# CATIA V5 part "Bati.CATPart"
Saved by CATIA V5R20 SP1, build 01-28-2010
Part number: Bati
Publications: "Corps principal"
Bounding box of the stored display mesh (mm): x -17.479 to 17.479, y -15.2 to 67.3, z -21.828 to 5.5
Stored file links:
  C:\Documents and Settings\pschann\Bureau\IAO\Bati.CATPart
  C:\Documents and Settings\pschann\Bureau\IAO\pschann.CATProduct
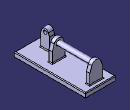
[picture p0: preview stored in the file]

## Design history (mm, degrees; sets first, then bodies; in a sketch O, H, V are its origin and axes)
External parameters (linked from other documents)
  `External.Diamètre coulisseau` = 10 mm
  `External.Epaisseur pivot` = 2 mm
  External.AB = 10 mm
  `External.Diamètre pivot` = 4 mm
  External.BC = 41 mm
  `External.Longueur axe pivot` = 6 mm
Set1
  Line1: linked copy from another document
  Line2: linked copy from another document
Body1 (main body)
  Sketch1 on zx-plane, origin (0, 0, 0), H (-1, 0, 0), V (0, 0, 1)
    circle A1 centre (0, 0) radius 3
    point P1 (0, 0)
    radius A1 = 3 {= `External.Diamètre coulisseau` /2-`External.Epaisseur pivot`}
    coincidence: P1 O
  Pad1: profile Sketch1, direction (0, -1, 0), length -16.8 {= (-External.AB -`External.Diamètre pivot` )*1.20}, opposite side length 58.3 {= (External.AB +External.BC+`External.Diamètre pivot` /2 )*1.1}
  Sketch2 on start face of Pad1, origin (0, 58.3, 0), H (-1, 0, 0), V (0, 0, 1)
    arc A1 centre (0, 0) radius 5.5 from (5.2004, 1.7906) to (-5.2004, 1.7906) ccw
    point P1 (-5.2004, 1.7906)
    point P2 (5.2004, 1.7906)
    reference projected line E1 (0, 12) -> (0, 0) from Line1
    line L1 (5.2004, 1.7906) -> (7.4793, -4.828)
    line L2 (-5.2004, 1.7906) -> (-7.4793, -4.828)
    point P4 (-7.4793, -4.828)
    line L3 (-7.4793, -4.828) -> (-7.4793, -16.828)
    point P6 (-7.4793, -4.828)
    line L4 (7.4793, -4.828) -> (7.4793, -16.828)
    line L5 (7.4793, -16.828) -> (-7.4793, -16.828)
    length L2 = 7
    length L1 = 7 {= Sketch2.length(L2)}
    length L4 = 12 {= External.AB *1.2}
    radius A1 = 5.5
    angle L2 L1 = 38
    symmetry: P2 P1 E1
    tangency: L1 A1, L2 A1
    vertical: L4 V, L3 V
    coincidence: P6 P4
    horizontal: L5 H
  Pad2: profile Sketch2, direction (0, 1, 0), length 4
  Sketch3 on end face of Pad1, origin (0, 16.8, 0), H (1, 0, 0), V (0, 0, 1)
    point P1 (-5.2004, 1.7906)
    point P2 (5.2004, 1.7906)
    arc A1 centre (0, 0) radius 5.5 from (5.2004, 1.7906) to (-5.2004, 1.7906) ccw
    line L1 (5.2004, 1.7906) -> (7.4793, -4.828)
    point P5 (-7.4793, -4.828)
    line L2 (-5.2004, 1.7906) -> (-7.4793, -4.828)
    point P7 (-7.4793, -4.828)
    line L3 (-7.4793, -4.828) -> (-7.4793, -16.828)
    line L4 (7.4793, -4.828) -> (7.4793, -16.828)
    line L5 (7.4793, -16.828) -> (-7.4793, -16.828)
    reference projected point E1 (0, 0) from Line2
    reference projected line E2 (7.0085, -16.828) -> (-7.0085, -16.828) from edge [start face of Pad2 | face of Pad2 from Sketch2.L5]
    length L4 = 12 {= Sketch2.length(L4)}
    length L1 = 7 {= Sketch2.length(L2)}
    radius A1 = 5.5 {= Sketch2.radius(A1)}
    length L2 = 7 {= Sketch3.length(L1)}
    horizontal: L5 H
    vertical: L4 V, L3 V
    tangency: L2 A1, L1 A1
    concentricity: E1 A1
    symmetry: P2 P1 V
    coincidence: P7 P5, L5 E2
  Pad3: profile Sketch3, direction (0, -1, 0), length 2, opposite side length 2
  Sketch4 on face of Pad2 from Sketch2.L5, origin (0, 0, -16.828), H (1, 0, 0), V (0, -1, 0)
    line L1 (-17.4793, 15.2) -> (17.4793, 15.2)
    line L2 (17.4793, 15.2) -> (17.4793, -67.3)
    line L3 (17.4793, -67.3) -> (-17.4793, -67.3)
    line L4 (-17.4793, -67.3) -> (-17.4793, 15.2)
    reference projected line E1 (-7.4793, -21.55) -> (-7.4793, -17.55) from edge [face of Pad3 from Sketch3.L5 | face of Pad3 from Sketch3.L3]
    reference projected line E2 (7.4793, -21.55) -> (7.4793, -17.55) from edge [face of Pad3 from Sketch3.L4 | face of Pad3 from Sketch3.L5]
    reference projected line E3 (7.4793, -62.3) -> (-7.4793, -62.3) from edge [face of Pad2 from Sketch2.L5 | end face of Pad2]
    reference projected line E4 (-7.4793, -14.8) -> (7.4793, -14.8) from edge [face of Pad3 from Sketch3.L5 | end face of Pad3]
    distance L4 E1 = 10
    distance L2 E2 = 10
    distance L3 E3 = 5
    distance L1 E4 = 30
    horizontal: L1 H, L3 H
    vertical: L2 V, L4 V
  Pad4: profile Sketch4, direction (0, 0, -1), length 5
  Sketch5 on yz-plane, origin (0, 0, 0), H (0, 1, 0), V (0, 0, 1)
    arc A1 centre (0, 0) radius 4 from (3.7821, 1.3023) to (-3.7821, 1.3023) ccw
    point P1 (-3.7821, 1.3023)
    point P2 (3.7821, 1.3023)
    line L1 (-3.7821, 1.3023) -> (-5.0843, -2.4798)
    line L2 (3.7821, 1.3023) -> (5.0843, -2.4798)
    line L3 (5.0843, -2.4798) -> (5.0843, -16.828)
    line L4 (5.0843, -16.828) -> (-5.0843, -16.828)
    line L5 (-5.0843, -16.828) -> (-5.0843, -2.4798)
    reference intersected line E1 (-12.45, -16.828) -> (90.2, -16.828) from start face of Pad4
    circle A2 centre (0, 0) radius 2
    point P7 (0, 0)
    radius A1 = 4 {= `External.Diamètre pivot`}
    angle L1 L2 = 38
    length L2 = 4 {= Sketch5.length(L1)}
    length L1 = 4
    radius A2 = 2 {= `External.Diamètre pivot` /2}
    tangency: L1 A1, L2 A1
    symmetry: P1 P2 V
    vertical: L3 V, L5 V
    horizontal: L4 H
    coincidence: L4 E1, P7 V
    concentricity: A2 A1
  Pad5: profile Sketch5, direction (1, 0, 0), length -3 {= -`External.Longueur axe pivot` /2}, opposite side length 9 {= `External.Longueur axe pivot` *1.5}
  Fillet1: radius 0.8, on start face of Pad4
